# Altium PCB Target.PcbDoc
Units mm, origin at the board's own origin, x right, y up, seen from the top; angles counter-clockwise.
Board outline 61.21 x 57.91 mm, 2 copper layers (Top Layer, Bottom Layer); 37 components, 30 nets, 131 pads, 26 vias.
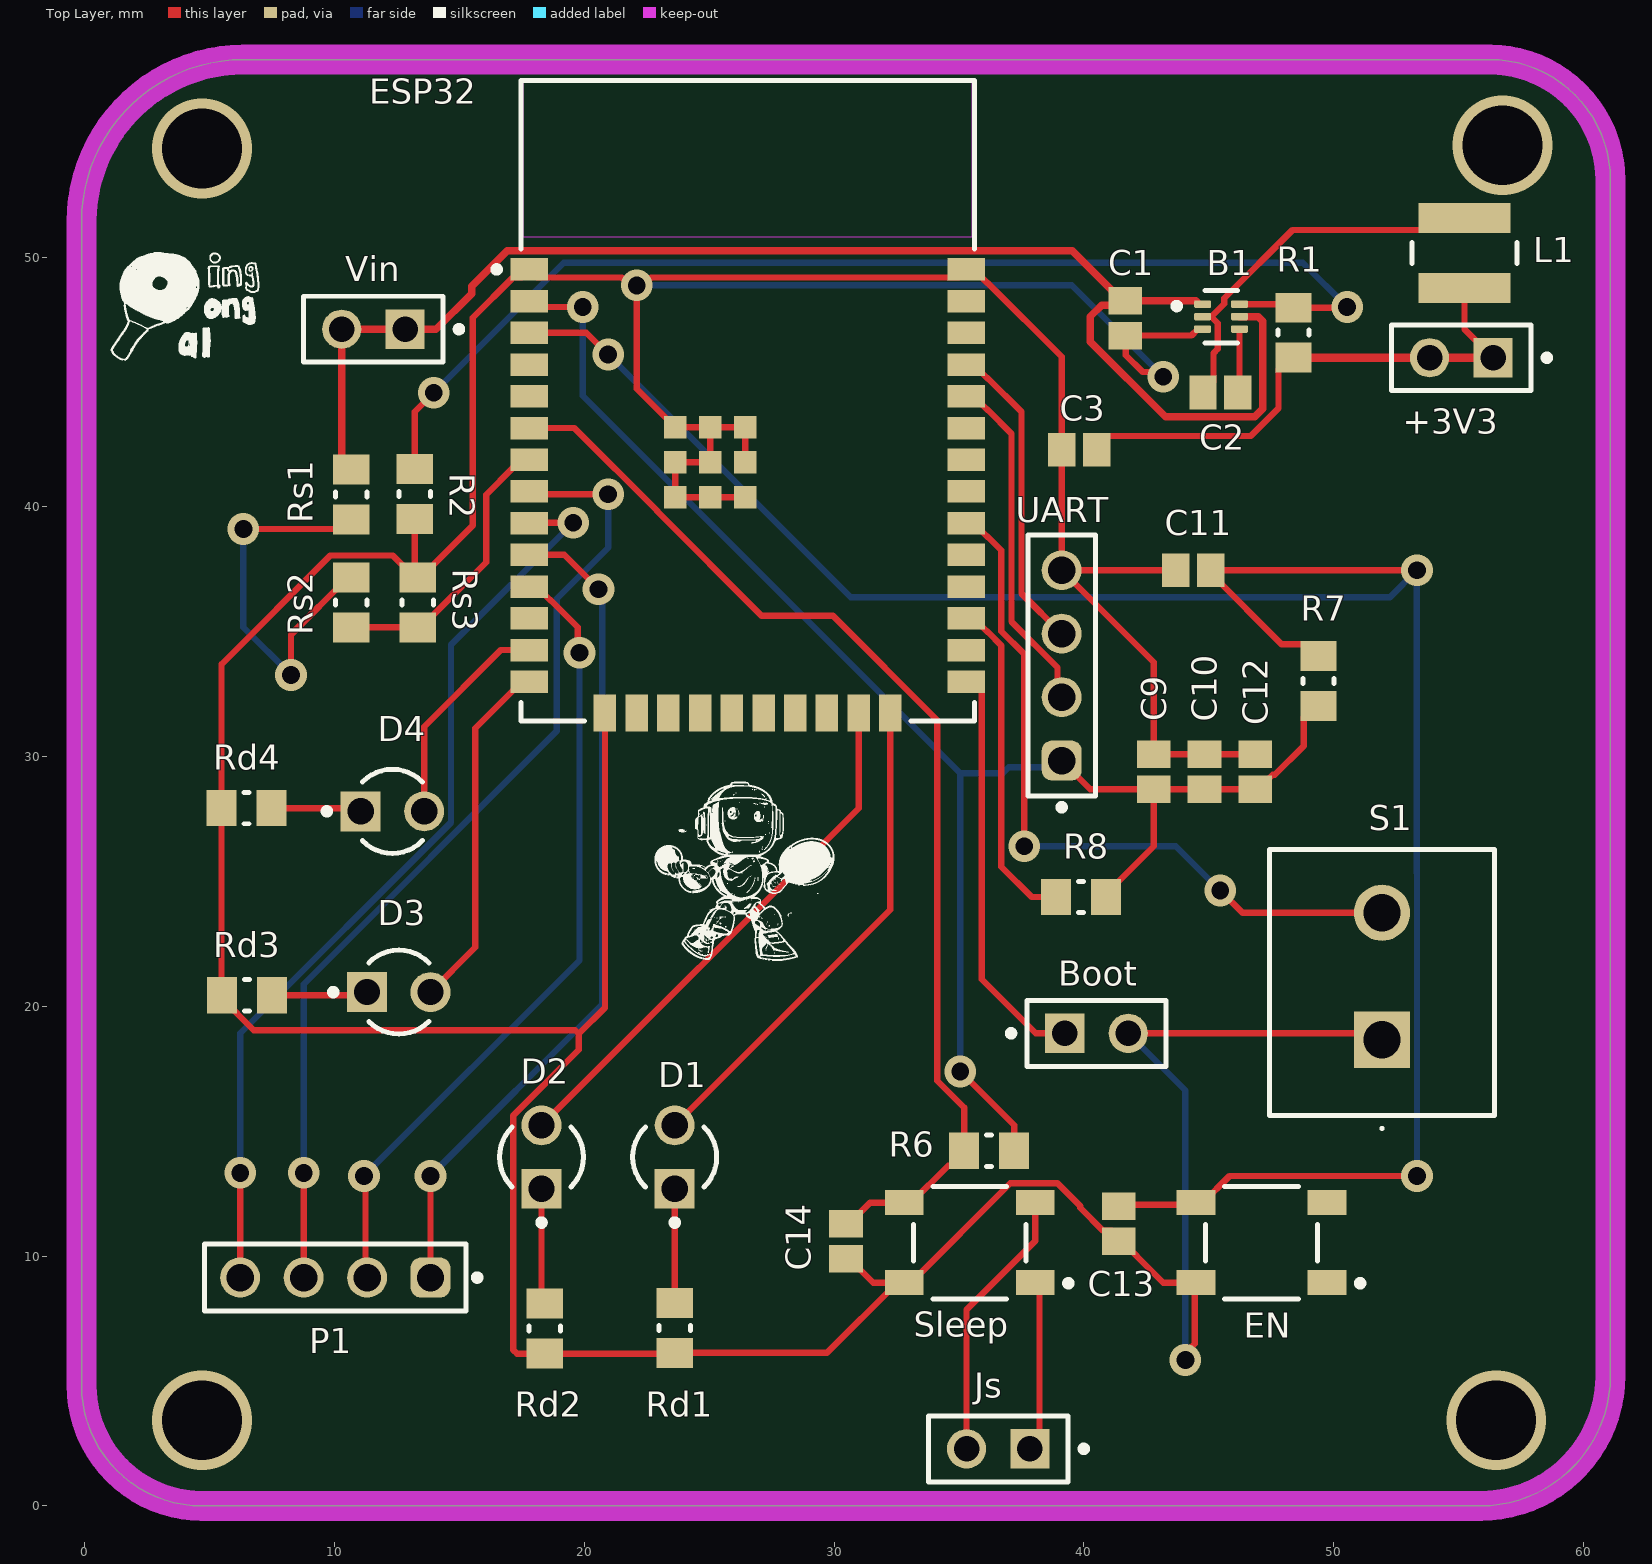
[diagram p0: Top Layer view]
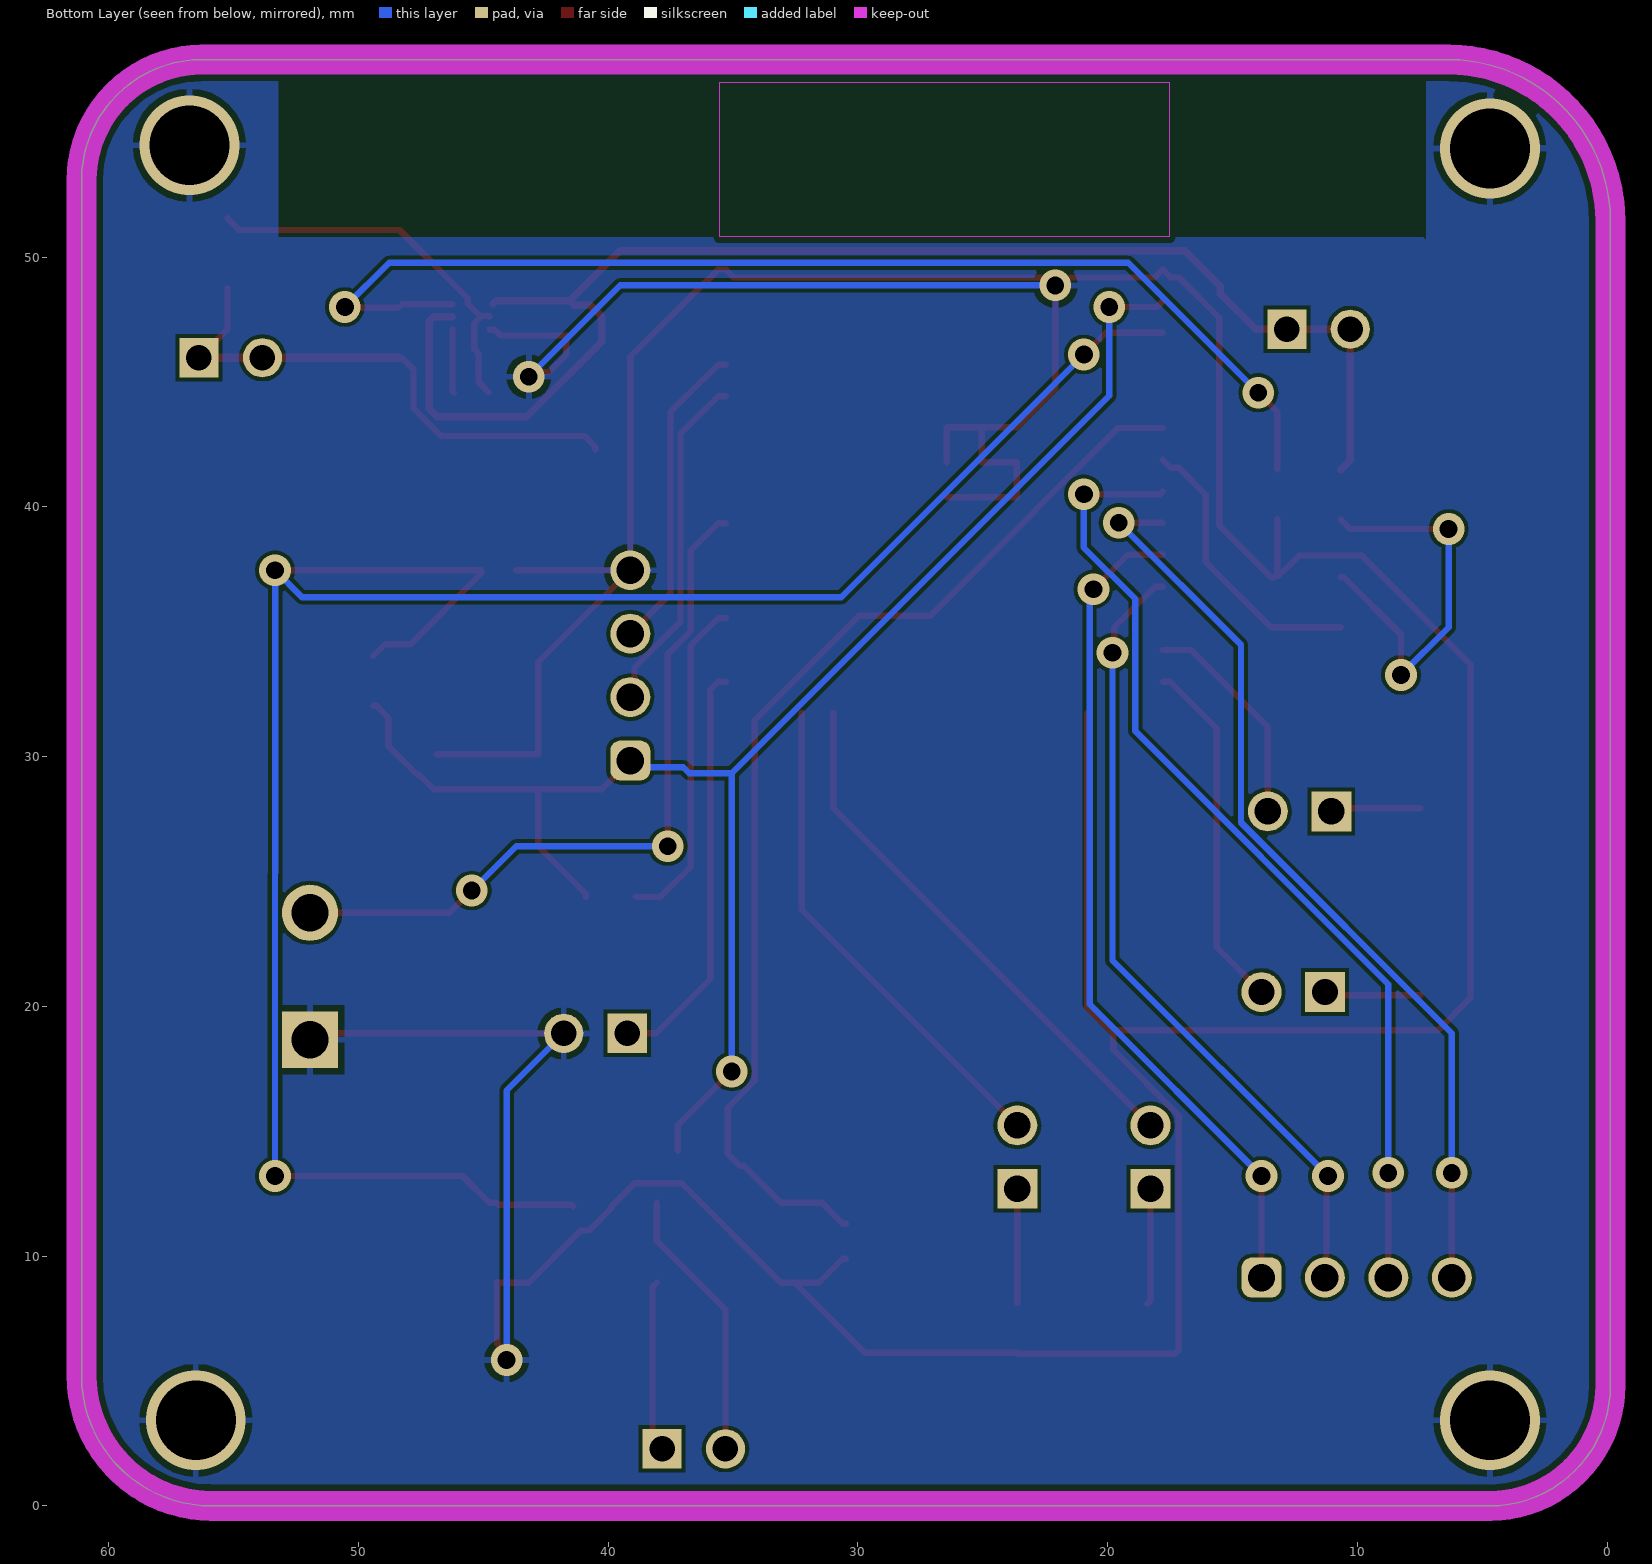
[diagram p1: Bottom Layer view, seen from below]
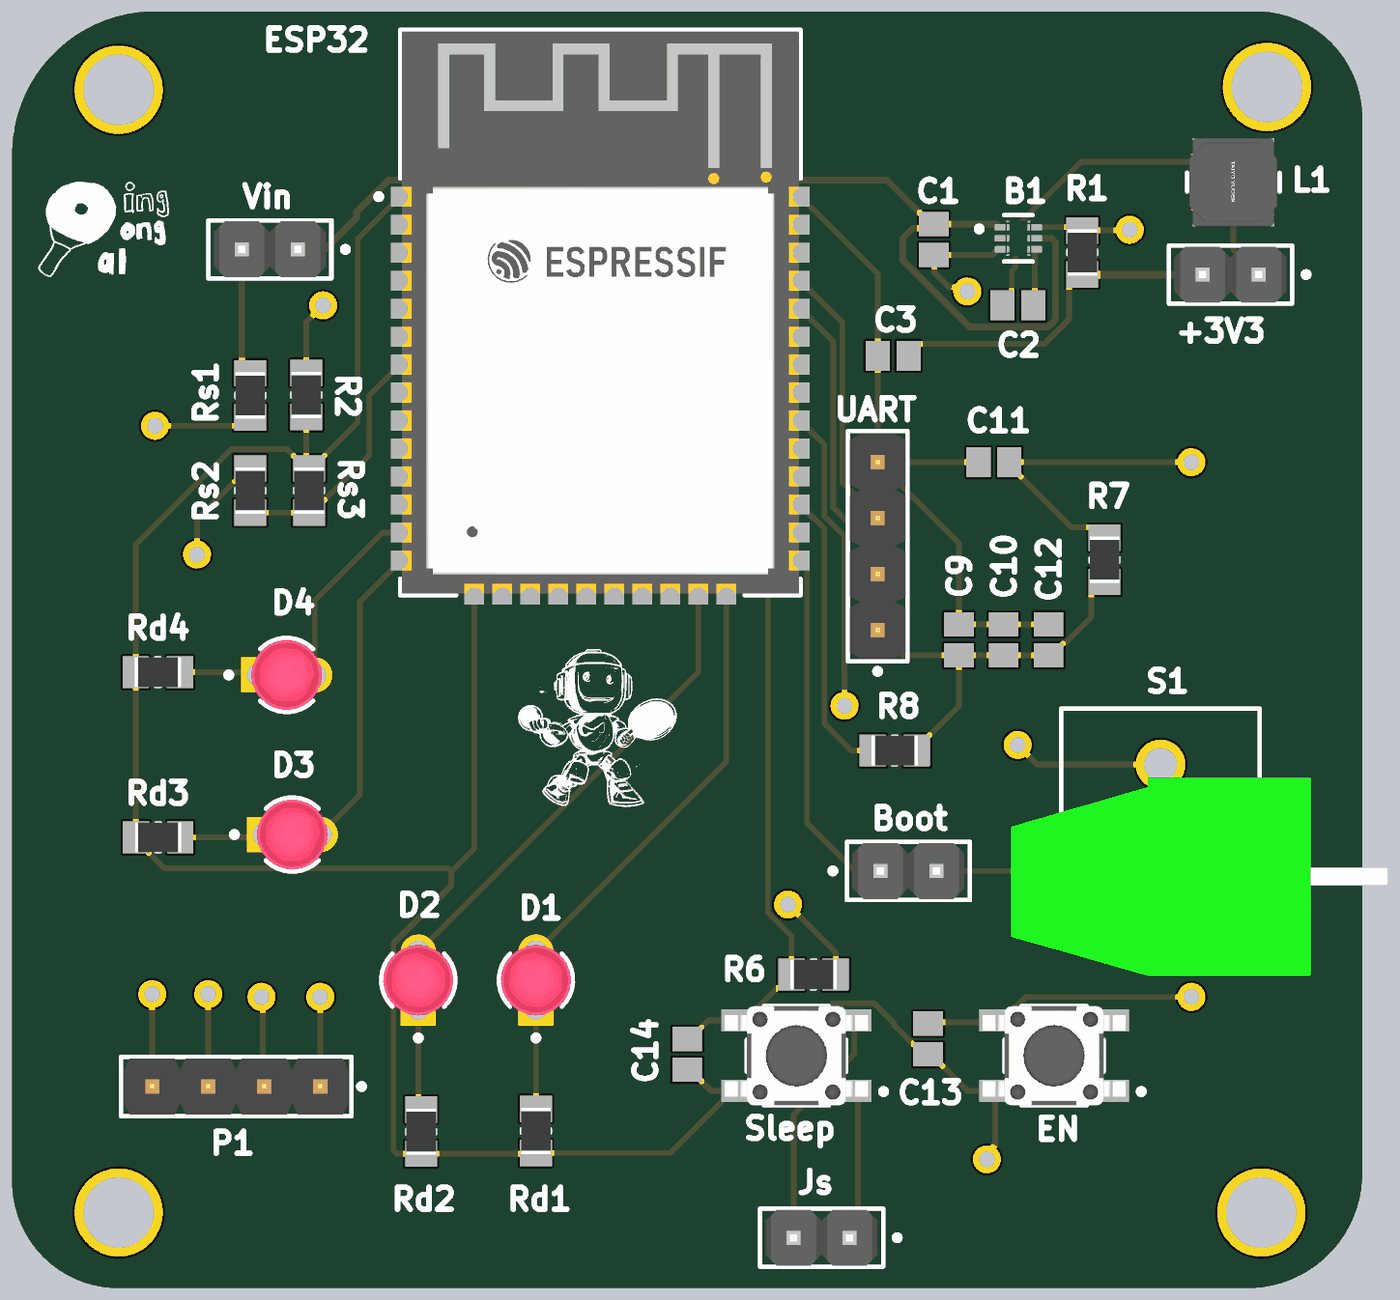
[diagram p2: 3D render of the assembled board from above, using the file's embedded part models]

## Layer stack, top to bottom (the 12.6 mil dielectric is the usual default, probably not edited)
Top Solder: solder mask 0.0102, Solder Resist, Dk 3.5
Top Layer: signal copper 0.0356
Dielectric 1: dielectric 0.32, FR-4, Dk 4.8
Bottom Layer: signal copper 0.0356
Bottom Solder: solder mask 0.0102, Solder Resist, Dk 3.5

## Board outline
4.699,0 cw(c4.699,4.826) -0.127,4.826 -0.127,51.435 cw(c6.35,51.435) 6.35,57.912 56.261,57.912 cw(c56.261,53.086) 61.087,53.086 61.087,5.207 cw(c55.88,5.207) 55.88,0

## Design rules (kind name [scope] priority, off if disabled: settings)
Clearance Clearance_1 [OnMid vs OnMid] p1: gap=0.15 ignorepadtopadclearanceinfootprint=FALSE sourcerule=37 cellrowname=All cellrowtype=0 cellcolname=All cellcoltype=0 innerlayers=TRUE
Clearance Clearance_2 [(ExistsOnLayer('Top Layer') Or ExistsOnLayer('Bottom Layer')) vs (ExistsOnLayer('Top Layer') Or ExistsOnLayer('Bottom Layer'))] p2: gap=0.15 ignorepadtopadclearanceinfootprint=FALSE sourcerule=37 cellrowname=All cellrowtype=0 cellcolname=All cellcoltype=0 outerlayers=TRUE
Clearance [All] p3: gap=0.254 ignorepadtopadclearanceinfootprint=FALSE ismatrix=TRUE
HoleSize [All] p1: absolutevalues=TRUE maxlimit=5 minlimit=0.025 maxpercent=80.000 minpercent=20.000
MinimumSolderMaskSliver [All] p1: minsoldermaskwidth=0.09
NetAntennae [IsPad] p1: netantennaetolerance=0
PlaneConnect [All] p1: planeconnectstyle=Direct reliefexpansion=0.508 reliefentries=4 reliefconductorwidth=0.254 reliefairgap=0.254
PolygonConnect [All] p1: connectstyle=Relief reliefconductorwidth=0.254 reliefentries=4 polygonreliefangle="90 Angle" airgapwidth=0.254
RoutingVias [All] p1: holewidth=0.711 width=1.27 viastyle="Through Hole" minholewidth=0.711 minwidth=1.27 maxholewidth=0.711 maxwidth=1.27
SilkToSolderMaskClearance [IsPad] p1: minsilkscreentomaskgap=0.15 clearancetoexposedcopper=TRUE
SolderMaskExpansion [All] p1: expansion=0.102 istentingtop=FALSE
SupplyNets "Schematic Supply Nets_1" [InNet('GND')] p1: voltage=0.000
Width MaxMinWidth_1 [All] p1: maxlimit=0.5 minlimit=0.254 preferedwidth=0.254 minimp=50.000000 maximp=50.000000 favimp=50.000000
25 further rules are at their usual default settings.

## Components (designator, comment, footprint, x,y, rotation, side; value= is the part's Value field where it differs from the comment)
+3V3 "M20-9990246" FP-M20-9990246-MFG 55.118,45.974 r180 top
B1 "TPS562231DRLR" FP-DRL0006A-MFG 45.497,47.62 r0 top
Boot "M20-9990246" FP-M20-9990246-MFG 40.513,18.923 r0 top
C1 "10uF" CAPC2013X88X50LL20T25 41.665,47.563 r270 top
C2 "0.1uF" CAPC2013X88X50LL20T25 45.475,44.58 r0 top
C3 "47uF" CAPC2013X88X50LL20T25 39.816,42.291 r180 top
C9 "22uF" CAPC2013X88X50LL20T25 42.799,29.402 r90 top
C10 "0.1uF" CAPC2013X88X50LL20T25 44.831,29.399 r90 top
C11 "0.1uF" CAPC2013X88X50LL20T25 44.388,37.465 r0 top
C12 "10uF" CAPC2013X88X50LL20T25 46.863,29.402 r90 top
C13 "0.1uF" CAPC2013X88X50LL20T25 41.402,11.303 r270 top
C14 "0.1uF" CAPC2013X88X50LL20T25 30.48,10.603 r270 top
D1 "VSLB3940" FP-VSLB3940-MFG 23.622,13.97 r90 top
D2 "VSLB3940" FP-VSLB3940-MFG 18.288,13.97 r90 top
D3 "VSLB3940" FP-VSLB3940-MFG 12.573,20.574 r0 top
D4 "VSLB3940" FP-VSLB3940-MFG 12.319,27.813 r0 top
EN "PTS647SK38SMTR2LFS" FP-PTS647SK38SMTR2LFS-MFG 47.117,10.541 r180 top
ESP32 "ESP32-WROOM-32E" FP-ESP32-WROOM-32E_M113EH-MFG 26.543,44.25 r0 top
Js "M20-9990246" FP-M20-9990246-MFG 36.576,2.286 r180 top
L1 "3.3uH" FP-NR4012-MFG 55.245,50.165 r270 top
P1 "61300411121" 61300411121 10.033,9.144 r180 top
R1 "45k" RESC2013X60X35ML10T20 48.396,46.977 r270 top
R2 "10k" RESC2013X60X35ML10T20 13.208,40.513 r90 top
R6 "10k" RESC2013X60X35ML10T20 36.211,14.224 r0 top
R7 "10k" RESC2013X60X35ML10T20 49.403,33.036 r90 top
R8 "10k" RESC2013X60X35ML10T20 39.894,24.384 r0 top
Rd1 "100" RESC2013X60X35ML10T20 23.622,7.128 r270 top
Rd2 "100" RESC2013X60X35ML10T20 18.415,7.096 r270 top
Rd3 "100" RESC2013X60X35ML10T20 6.493,20.447 r180 top
Rd4 "100" RESC2013X60X35ML10T20 6.477,27.94 r180 top
Rs1 "100k" RESC2013X60X35ML10T20 10.668,40.497 r90 top
Rs2 "100k" RESC2013X60X35ML10T20 10.668,36.179 r90 top
Rs3 "100k" RESC2013X60X35ML10T20 13.335,36.179 r270 top
S1 "EBAFA-02-D" EBAFA02D 51.943,18.669 r90 top
Sleep "PTS647SK38SMTR2LFS" FP-PTS647SK38SMTR2LFS-MFG 35.433,10.541 r180 top
UART "61300411121" 61300411121 39.116,33.655 r90 top
Vin "M20-9990246" FP-M20-9990246-MFG 11.557,47.117 r180 top

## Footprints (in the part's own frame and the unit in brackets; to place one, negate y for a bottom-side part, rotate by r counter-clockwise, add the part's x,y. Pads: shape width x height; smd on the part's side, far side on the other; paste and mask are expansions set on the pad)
61300411121 [mm] "Pin Header, pitch 2.54 mm, THT, Vertical, single row, 4p"
  rrect50% 1.6x1.6 hole 1.1: 1(-3.81,0)
  round 1.6 hole 1.1: 2(-1.27,0) 3(1.27,0) 4(3.81,0)
  silkscreen extent -5.8,-1.35 5.23,1.35, body extent -5.08,-1.27 5.08,1.27, height 8.57
CAPC2013X88X50LL20T25 [mm] "Chip Capacitor, 2-Leads, Body 2.00x1.25mm, IPC High Density"
  rect 1.1x1.35 smd: 1(-0.7,0) 2(0.7,0)
  body extent -1.1,-0.72 1.1,0.72, height 0.88
EBAFA02D [mm]
  rect 2.25x2.25 hole 1.5: 1(0,0)
  round 2.25 hole 1.5: 2(5.08,0)
  silkscreen extent -3.6,-4.5 7.62,4.5, body extent -4.5,-10.3 4.5,6.8, height 5.08
FP-DRL0006A-MFG [mm]
  rrect33% 0.67x0.3 smd paste+0 mask+0: 1(-0.74,0.5) 2(-0.74,0) 3(-0.74,-0.5) 4(0.74,-0.5) 5(0.74,0) 6(0.74,0.5)
  silkscreen extent -1.9,-1.05 0.65,1.05, body extent -1.17,-1.1 1.17,1.1, height 0.25
FP-ESP32-WROOM-32E_M113EH-MFG [mm]
  rect 1.5x0.9 smd paste+0 mask+0: 1(-8.75,5.26) 2(-8.75,3.99) 3(-8.75,2.72) 4(-8.75,1.45) 5(-8.75,0.18) 6(-8.75,-1.09) 7(-8.75,-2.36) 8(-8.75,-3.63) 9(-8.75,-4.9) 10(-8.75,-6.17) 11(-8.75,-7.44) 12(-8.75,-8.71) 13(-8.75,-9.98) 14(-8.75,-11.25) 25(8.75,-11.25) 26(8.75,-9.98) 27(8.75,-8.71) 28(8.75,-7.44) 29(8.75,-6.17) 30(8.75,-4.9) 31(8.75,-3.63) 32(8.75,-2.36) 33(8.75,-1.09) 34(8.75,0.18) 35(8.75,1.45) 36(8.75,2.72) 37(8.75,3.99) 38(8.75,5.26)
  rect 0.9x1.5 smd paste+0 mask+0: 15(-5.715,-12.5) 16(-4.445,-12.5) 17(-3.175,-12.5) 18(-1.905,-12.5) 19(-0.635,-12.5) 20(0.635,-12.5) 21(1.905,-12.5) 22(3.175,-12.5) 23(4.445,-12.5) 24(5.715,-12.5)
  rect 0.9x0.9 smd paste+0 mask+0: 39(-2.9,-3.86) 39(-2.9,-2.46) 39(-2.9,-1.06) 39(-1.5,-3.86) 39(-1.5,-2.46) 39(-1.5,-1.06) 39(-0.1,-3.86) 39(-0.1,-2.46) 39(-0.1,-1.06)
  Keep-Out Layer region: -9.002,6.559 8.998,6.559 8.998,12.749 -9.002,12.749
  silkscreen extent -10.17,-12.83 9.08,12.83, body extent -9.6,-13.35 9.6,12.93, height 0.25
FP-M20-9990246-MFG [mm]
  rect 1.57x1.57 hole 1.02 paste-2539.97 mask+0: 1(-1.27,0)
  round 1.57 hole 1.02 paste-2539.97 mask+0: 2(1.27,0)
  silkscreen extent -3.55,-1.32 2.79,1.32, body extent -2.89,-1.42 2.89,1.42, height 0.25
FP-NR4012-MFG [mm]
  rect 1.2x3.7 smd paste+0 mask+0: 1(-1.4,0) 2(1.4,0)
  silkscreen extent -0.43,-2.1 0.43,2.1, body extent -2.2,-2.2 2.2,2.2, height 0.25
FP-PTS647SK38SMTR2LFS-MFG [mm]
  rect 1.55x1 smd paste+0 mask+0: 1(-2.625,1.6) 2(2.625,1.6) 3(-2.625,-1.6) 4(2.625,-1.6)
  silkscreen extent -4.08,-2.25 2.25,2.25, body extent -3.5,-2.35 3.5,2.35, height 0.25
FP-VSLB3940-MFG [mm]
  rect 1.6x1.6 hole 1.05 paste-2539.97 mask+0: 1(-1.27,0)
  round 1.6 hole 1.05 paste-2539.97 mask+0: 2(1.27,0)
  silkscreen extent -2.75,-1.68 1.2,1.68, body extent -2.32,-2.32 2.32,2.32, height 0.25
RESC2013X60X35ML10T20 [mm] "Chip Resistor, 2-Leads, Body 2.1x1.35mm, IPC Low Density"
  rect 1.2x1.45 smd: 1(-1,0) 2(1,0)
  silkscreen extent -0.1,-0.63 0.1,0.63, body extent -1.05,-0.68 1.05,0.67, height 0.6

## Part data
+3V3 Boot Js Vin: library part CMP-15831-000009-1, "CONN HEADER VERT 2POS 2.54MM", Current rating=3A, Manufacturer=Harwin, Temperature="-40°C to +105°C", Temperature Range High=+105°C, Temperature Range Low=-40°C
B1: library part CMP-04918-000372-1, "POWER MANAGEMENT"
C1 C2 C3 C9 C10 C11 C12 C13 C14: library part CMP-2007-00266-1, Manufacturer=Kemet, Part Number=C0805C103K5RACTU
D1 D2 D3 D4: library part CMP-00030-18785862-1, "VSLB3940 940 nm 100 mA ±22° Through Hole High Speed Infrared Emitting Diode - T-1", Case/Package=T, Forward Current=100mA, Forward Voltage=1.35V, Max Operating Temperature=85°C, Max Power Dissipation=160mW, Min Operating Temperature=-25°C, Reverse Voltage=5V
EN Sleep: library part CMP-10040-000033-1, "TACT 4.5 X 4.5, 3.8 MM H, 2.5N,", Max Operating Temperature=70°C, Min Operating Temperature=-20°C, Operating Force=250gf, Ratings=IP40
ESP32: library part CMP-194065-000012-1, "RX TXRX MOD WIFI TRACE ANT SMD"
L1: library part CMP-14484-001001-1, "SMD Power Inductors 3.3uH ±20% 1.4A 84mΩ", Case/Package=4012, Current rating=1.7A, DC Resistance (DCR)=84mR, Inductance Tolerance=20%, Max Operating Temperature=125°C, Min Operating Temperature=-25°C, Package Quantity=1, Resistor Type=Wirewound, Saturation Current=1.4A, Self Resonant Frequency=60MHz, Test Frequency=100kHz
P1 UART: library part CMP-1502-01064-3, Color=Black, Contact Resistance=20mΩ, Current rating=3A, Max Operating Temperature=105°C, Min Operating Temperature=-40°C, Operating Supply Voltage=250V
R1 R2 R6 R7 R8 Rd1 Rd2 Rd3 Rd4 Rs1 Rs2 Rs3: library part CMP-2100-03671-1, "Chip Resistor, 1 KOhm, +/- 1%, 125 mW, -55 to 155 degC, 0805 (2012 Metric), RoHS, Tape and Reel", Case Code (Imperial)=0805, Case Code (Metric)=2012, Manufacturer=Yageo, Max Operating Temperature=155degC, Max Power Dissipation=125mW, Min Operating Temperature=-55degC, Package Description="2-Pin Surface Mounted Device, Body 2 x 1.25 mm", Package Quantity=1, Resistance=1KOhm, Temperature Coefficient=100ppm/degreesC, Tolerance=1%, Voltage rating=150V
S1: "Connector", Manufacturer_Name="Adam Tech"

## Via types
v1: diameter 1.27, hole 0.711, Top Layer to Bottom Layer, 22 vias
v2: diameter 4, hole 3.2, Top Layer to Bottom Layer, 4 vias

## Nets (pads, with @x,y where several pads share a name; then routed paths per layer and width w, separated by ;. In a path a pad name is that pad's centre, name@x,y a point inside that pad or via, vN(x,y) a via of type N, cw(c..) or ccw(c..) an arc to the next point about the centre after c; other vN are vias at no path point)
+3V3: C9.1 C10.1 C12.1 ESP32.2 R6.2 R7.1 R8.2 UART.1 | length 65.4
  Top Layer w0.254: ESP32.2 18.027,48.006 v1(19.939,48.006) ; v1(35.052,17.399) 37.211,15.24 R6.2 ; UART.1 40.259,28.702 C9.1 ; R8.2 40.894,24.509 42.799,26.414 C9.1 ; R7.1 49.278,32.036 48.805,31.563 48.805,30.427 47.653,29.275 47.561,29.275 46.988,28.702 C12.1 46.86,28.699 C10.1 44.828,28.702 C9.1
  Bottom Layer w0.254: v1(19.939,48.006) 19.939,44.45 35.052,29.337 ; v1(35.052,17.399) 35.052,29.337 ; UART.1 38.843,29.572 36.991,29.572 36.756,29.337 35.052,29.337
+6.4V: B1.1 B1.5 C1.1 Rs1.2 Vin.1 Vin.2 | length 57.8
  Top Layer w0.3: Rs1.2 10.287,41.878 Vin.2 14.062,47.117 15.49,48.545 15.49,48.832 16.919,50.26 39.543,50.26 C1.1@41.54,48.263 ; B1.1@44.596,48.145 44.478,48.263 C1.1@41.54,48.263 ; B1.5 46.995,47.62 47.171,47.444 47.171,43.927 46.849,43.605 43.273,43.605 40.259,46.619 40.259,47.625 40.715,48.081 41.358,48.081 C1.1@41.54,48.263
Boot: Boot.1 ESP32.25 | length 16.6
  Top Layer w0.254: ESP32.25 35.593,33 35.916,32.677 35.916,21.084 38.077,18.923 Boot.1
EN: C11.2 C13.1 EN.4 ESP32.3 R7.2 | length 90.9
  Top Layer w0.254: ESP32.3 20.086,46.97 v1(20.955,46.101) ; C13.1 41.456,12.057 44.408,12.057 EN.4 44.767,12.141 45.836,13.211 v1(53.343,13.211) ; R7.2 48.93,34.509 47.919,34.509 45.088,37.34 C11.2 v1@53.086,37.465
  Bottom Layer w0.254: v1(20.955,46.101) 30.668,36.388 52.263,36.388 v1(53.34,37.465) 53.34,25.34 53.345,25.335 53.345,13.213 v1(53.343,13.211)
GND: B1.3 Boot.2 C1.2 C3.2 C9.2 C10.2 C11.1 C12.2 C13.2 C14.2 EN.2 ESP32.1 ESP32.15 ESP32.38 ESP32.39 R2.1 Rd1.2 Rd2.2 Rd3.2 Rd4.2 Rs3.1 S1.1 Sleep.2 UART.4 | length 239.2
  Top Layer w0.254: Rs3.1@13.146,37.244 12.333,38.056 9.828,38.056 5.477,33.705 5.477,20.338 6.767,19.048 19.636,19.048 19.783,18.901 19.785,18.901 20.828,19.944 ESP32.15 ; R2.1 13.208,37.306 Rs3.1 13.46,37.179 15.541,39.26 15.541,47.579 17.148,49.187 17.47,49.187 ESP32.1 18.116,49.187 21.508,49.187 21.673,49.022 v1@22.098,49.022 ; 19.785,18.899 19.785,18.26 17.16,15.635 17.16,6.245 17.309,6.096 23.59,6.096 Rd1.2 29.72,6.128 Sleep.2@32.533,8.941 ; ESP32.39@26.443,40.39 23.643,40.39 23.643,41.79 25.043,41.79 ESP32.39@25.043,43.19 ; ESP32.39@26.443,41.79 26.443,43.19 ESP32.39@25.043,43.19 ; C14.2 30.605,9.903 31.567,8.941 Sleep.2@32.533,8.941 ; Boot.2 51.689,18.923 S1.1 ; v1(43.18,45.212) 42.986,45.406 42.357,45.406 41.683,46.081 41.683,46.845 C1.2 44.314,46.863 44.548,47.097 44.733,47.097 B1.3 ; C11.1 UART.4 ; v1(44.069,5.842) 44.069,6.117 44.45,6.498 44.45,8.899 EN.2 43.189,8.941 41.104,11.026 40.762,11.026 39.855,11.933 39.855,12.011 38.948,12.918 37.06,12.918 33.083,8.941 Sleep.2@32.533,8.941 ; C12.2 44.834,30.102 C10.2 44.828,30.102 C9.2 42.799,33.782 UART.4 ; v1@22.098,49.022 22.523,49.022 22.688,49.187 34.97,49.187 ESP32.38 35.593,49.51 36.136,48.967 36.158,48.967 39.116,46.009 UART.4 ; v1@22.098,49.022 22.098,44.735 23.643,43.19 ESP32.39@25.043,43.19
  Bottom Layer w0.254: v1(22.098,48.872) 39.52,48.872 v1(43.18,45.212) ; Boot.2 44.069,16.637 v1(44.069,5.842)
  other v2: 4.699,3.429 56.515,3.429 4.699,54.356 56.769,54.483
IO25: ESP32.10 P1.1 | length 33.8
  Top Layer w0.254: P1.1 v1(13.843,13.208) ; ESP32.10 19.197,38.08 v1(20.574,36.703)
  Bottom Layer w0.254: v1(13.843,13.208) 20.724,20.089 20.724,36.553 v1(20.574,36.703)
IO26: ESP32.11 P1.2 | length 32.4
  Top Layer w0.254: v1(11.176,13.208) 11.239,13.144 11.239,9.207 P1.2 ; ESP32.11 18.093,36.81 18.636,36.267 18.658,36.267 19.746,35.179 19.746,34.229 v1(19.812,34.163)
  Bottom Layer w0.254: v1(11.176,13.208) 19.812,21.844 19.812,34.036 v1@19.939,34.163
IO32: ESP32.8 P1.3 | length 39.6
  Top Layer w0.254: P1.3 v1(8.763,13.335) ; ESP32.8 17.9,40.513 v1(20.955,40.513)
  Bottom Layer w0.254: v1(8.763,13.335) 8.763,20.893 18.9,31.03 18.9,36.319 20.955,38.374 v1(20.955,40.513)
IO33: ESP32.9 P1.4 | length 37.5
  Top Layer w0.254: P1.4 v1(6.223,13.335) ; ESP32.9 17.813,39.37 v1(19.558,39.37)
  Bottom Layer w0.254: v1(6.223,13.335) 6.223,18.924 14.666,27.367 14.666,34.478 v1(19.558,39.37)
LED1: D1.2 ESP32.24 | length 20.1
  Top Layer w0.254: D1.2 32.258,23.876 ESP32.24
LED2: D2.2 ESP32.23 | length 21.8
  Top Layer w0.254: D2.2 30.988,27.94 ESP32.23
LED3: D3.2 ESP32.14 | length 14.2
  Top Layer w0.254: D3.2 15.635,22.366 15.635,31.142 17.493,33 ESP32.14
LED4: D4.2 ESP32.13 | length 8.9
  Top Layer w0.254: D4.2 13.589,31.197 16.662,34.27 ESP32.13
Net+3V3_1: +3V3.1 +3V3.2 C3.1 L1.2 R1.2 | length 21.6
  Top Layer w0.254: C3.1 40.516,42.416 40.939,42.839 46.687,42.839 47.798,43.95 47.798,45.504 48.271,45.977 R1.2 ; L1.2 55.245,47.117 +3V3.1
  Top Layer w0.35: R1.2@48.396,45.974 +3V3.1
NetB1_2: B1.2 C2.1 L1.1 | length 15.6
  Top Layer w0.254: B1.2 44.779,47.643 45.127,47.643 45.625,48.14 45.625,48.356 48.361,51.092 54.772,51.092 L1.1 ; C2.1 45.198,45.003 45.198,46.156 45.368,46.327 45.368,47.356 45.127,47.597
NetB1_4: B1.4 C2.2 | length 2.6
  Top Layer w0.254: C2.2 46.237,44.642 B1.4
NetB1_6: B1.6 R1.1 R2.2 | length 46.7
  Top Layer w0.254: R2.2 13.208,43.815 v1(13.97,44.577) ; B1.6 48.253,48.12 R1.1 50.009,47.977 v1@50.038,48.006
  Bottom Layer w0.254: v1(13.97,44.577) 19.177,49.784 48.768,49.784 v1(50.546,48.006)
NetD1_1: D1.1 Rd1.1 | length 4.6
  Top Layer w0.254: Rd1.1 D1.1
NetD2_1: D2.1 Rd2.1 | length 4.7
  Top Layer w0.254: D2.1 18.288,8.223 Rd2.1
NetD3_1: D3.1 Rd3.1 | length 3.9
  Top Layer w0.254: Rd3.1 11.176,20.447 D3.1
NetD4_1: D4.1 Rd4.1 | length 3.6
  Top Layer w0.254: Rd4.1 10.922,27.94 D4.1
NetESP32_27: ESP32.27 R8.1 | length 13.4
  Top Layer w0.254: ESP32.27 35.593,35.54 36.136,34.997 36.158,34.997 36.703,34.452 36.703,25.594 37.913,24.384 R8.1
NetJs_1: Js.1 Sleep.1 | length 6.9
  Top Layer w0.254: Js.1 38.227,2.667 38.227,8.772 Sleep.1
NetJs_2: Js.2 Sleep.3 | length 11
  Top Layer w0.254: Js.2 35.306,7.856 38.058,10.608 Sleep.3
NetRs1_1: Rs1.1 Rs2.2 | length 16.1
  Top Layer w0.254: v1(6.35,39.116) 10.287,39.116 Rs1.1 ; v1(8.255,33.274) 8.255,34.891 10.543,37.179 Rs2.2
  Bottom Layer w0.254: v1(6.35,39.116) 6.35,35.179 v1(8.255,33.274)
PZE: ESP32.30 S1.2 | length 29.5
  Top Layer w0.254: ESP32.30 35.593,39.35 36.136,38.807 36.158,38.807 36.7,38.265 36.7,35.026 37.615,34.111 v1(37.615,26.416) ; v1(45.466,24.638) 46.355,23.749 S1.2
  Bottom Layer w0.254: v1(37.615,26.416) 43.688,26.416 v1(45.466,24.638)
RXD0: ESP32.34 UART.2 | length 13.8
  Top Layer w0.254: ESP32.34 35.593,44.43 36.136,43.887 36.158,43.887 37.104,42.941 37.104,35.414 38.952,33.566 38.952,32.549 UART.2
Sleep: C14.1 ESP32.6 R6.1 Sleep.4 | length 44.9
  Top Layer w0.254: ESP32.6 19.598,43.16 22.916,39.842 22.916,39.825 27.099,35.642 29.957,35.642 34.14,31.46 34.14,17.021 35.211,15.95 35.211,14.099 34.738,13.626 34.568,13.626 33.083,12.141 31.443,12.141 30.605,11.303 C14.1
TXD0: ESP32.35 UART.3 | length 12.5
  Top Layer w0.254: ESP32.35 35.593,45.7 36.136,45.157 36.158,45.157 37.508,43.807 37.508,36.533 UART.3
Vsense: ESP32.7 Rs2.1 Rs3.2 | length 11.5
  Top Layer w0.254: Rs2.1 13.46,35.179 16.071,37.79 16.071,40.49 17.148,41.567 17.47,41.567 ESP32.7
pads on no net: EN.1 EN.3 ESP32.4 ESP32.5 ESP32.12 ESP32.16 ESP32.17 ESP32.18 ESP32.19 ESP32.20 ESP32.21 ESP32.22 ESP32.26 ESP32.28 ESP32.29 ESP32.31 ESP32.32 ESP32.33 ESP32.36 ESP32.37

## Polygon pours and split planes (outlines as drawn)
GND on Bottom Layer (solid, pour order 2): -0.119,4.818 ccw(c4.707,4.818) 4.707,-0.008 55.888,-0.008 ccw(c55.888,5.199) 61.095,5.199 61.095,53.078 ccw(c56.269,53.078) 56.269,57.904 6.358,57.904 ccw(c6.358,51.427) -0.119,51.427

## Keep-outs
Keep-Out Layer:
  the board outline again, w1.2

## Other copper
Bottom Layer:
  pour cut-out: 7.239,50.673 7.366,50.8 53.213,50.8 53.213,57.912 7.239,57.912

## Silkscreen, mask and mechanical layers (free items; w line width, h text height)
Top Overlay:
  drawing of 288 lines, arcs and shapes, not listed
